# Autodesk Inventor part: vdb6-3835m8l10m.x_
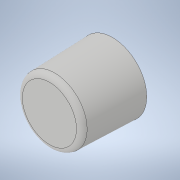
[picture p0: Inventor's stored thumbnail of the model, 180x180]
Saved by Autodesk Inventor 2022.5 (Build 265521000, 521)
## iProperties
Created: 2021-08
Part Number: vdb6-3835m8l10m.x_
Material: 一般
Document SubType Name: Modeling
Designer: ImaoCorp
Density: 1 g/cm^3
Appearance: 既定
Sending System: SOLIDWORKS 2019-2019304
MC: AMD64
MC_MODEL: Intel64 Family 6 Model 60 Stepping 3, GenuineIntel
OS: Windows_NT
FRU: Parasolid Version 31.0, build 290,  9- 1-2019
FORMAT: text
GUISE: transmit
KEY: vdb6-3835m8l10m
FILE: vdb6-3835m8l10m.x_t
DATE: Wed Aug 11 15:00:22 2021
Author: ImaoCorp
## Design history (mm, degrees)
feature "Base1"
node "ソリッド1"
